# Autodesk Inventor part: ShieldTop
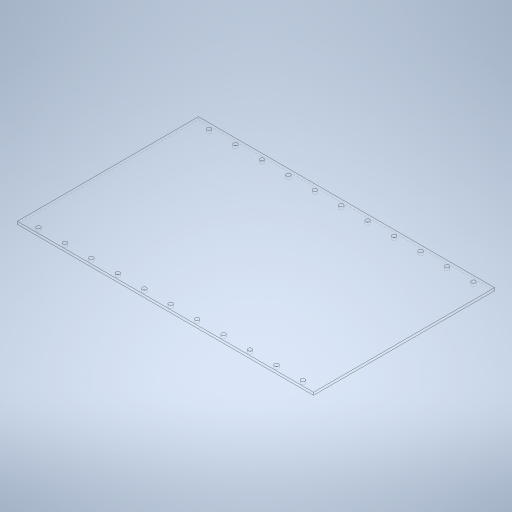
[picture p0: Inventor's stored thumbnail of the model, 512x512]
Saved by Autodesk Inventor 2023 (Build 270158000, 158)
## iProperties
Created: 2023-10
Part Number: ShieldTop
Material: Aluminum 7075
Document SubType Name: Modeling
Designer: tornqvih
Density: 2.81 g/cm^3
Appearance: Satin - Brushed Heavy
Author: tornqvih
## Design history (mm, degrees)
sketch "Sketch1"
  geometry: L1 (112, 68.5)-(-112, 68.5); L2 (-112, 68.5)-(-112, -68.5); L3 (-112, -68.5)-(112, -68.5); L4 (112, -68.5)-(112, 68.5); L5 (112, 68.5)-(-112, -68.5); L6 (-112, 68.5)-(112, -68.5); 1 further point
  constraints: 12 end point, 2 midpoint, 2 parallel, 1 horizontal, 1 perpendicular
  dimensions: "d0" = 137 distance of L3.end L1.start; "d1" = 224 distance of L1.start L1.end
extrude "Extrusion1" new body sketch "Sketch1" distance "d2" = 2; taper "d3" = 0 deg
sketch "Sketch2"
  geometry: L1 (112, 68.5)-(-112, 68.5) reference; L2 (-156.8, 0)-(156.8, 0) reference; L3 (-112, 68.5)-(-112, -68.5) reference; L4 (0, 95.9)-(0, -95.9) reference; 23 further points
  constraints: 16 symmetric about line, 5 horizontal alignment, 1 point on line, 1 vertical alignment
  dimensions: "d4" = 4 distance from line of L1 point (-100, 64.5); "d13" = 20 distance from line of L4 point (-20, 64.5); "d14" = 60 distance from line of L4 point (-60, 64.5); "d15" = 100 distance from line of L4 point (-100, 64.5); "d16" = 40 distance from line of L4 point (-40, 64.5); "d17" = 80 distance from line of L4 point (-80, 64.5)
hole "Hole1" sketch "Sketch2" diameter "d5" = 3; stored, may be unused: countersink angle "d9" = 90 deg, drill point angle "d11" = 118 deg; dims "d6" = 6, "d7" = 4, "d8" = 2, "d10" = 8
body "Solid1"
